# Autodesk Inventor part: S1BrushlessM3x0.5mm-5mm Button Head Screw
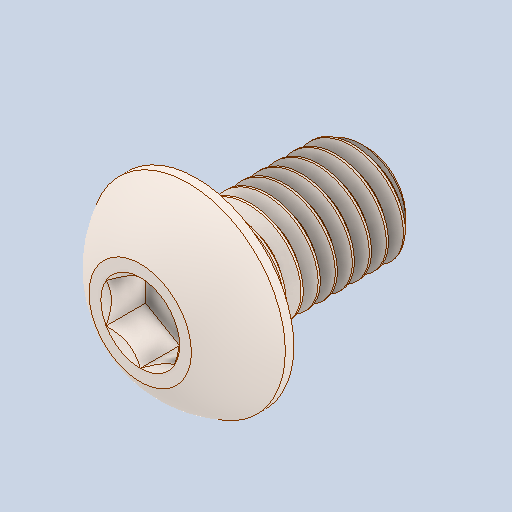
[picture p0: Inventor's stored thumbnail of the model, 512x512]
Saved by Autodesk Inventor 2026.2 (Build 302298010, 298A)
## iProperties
Created: 1601-01
Part Number: S1BrushlessM3x0.5mm-5mm Button Head Screw
Material: Alloy Steel
Document SubType Name: Modeling
Designer: mel
Density: 7.7 g/cm^3
Appearance: satin finish stainless steel
Author: mel
Sending System: SOLIDWORKS 2023
Part Number: M3x0
Last Saved Date: 2025-04-02
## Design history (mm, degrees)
feature "DeleteFace1"
node "Solide1"
